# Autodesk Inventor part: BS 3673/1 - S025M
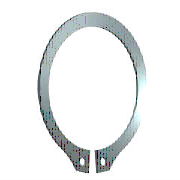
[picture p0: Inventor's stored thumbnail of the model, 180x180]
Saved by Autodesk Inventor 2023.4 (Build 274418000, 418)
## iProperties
Created: 2022-02
Part Number: BS 3673/1 - S025M
Material: Acier, doux
Description: Spécifications des anneaux élastiques - Anneaux élastiques en acier au carbone
Document SubType Name: Modeling
Standard: BS 3673/1
Designer: bruno
Standards Organization: BSI
Language: fr-FR
Size Designation: S025M
Categories: <MemberInstance><Categories><Category DisplayName="Pièces d'arbre" InternalName="7f7aeb1f-a693-4053-b835-cee3144e0d98" Mnemonic="SHFT"><Category DisplayName="An
Density: 7.85 g/cm^3
Appearance: Semi-poli
IsCustomPart: 0
Author: bruno
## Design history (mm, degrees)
sketch "Esquisse1"
  geometry: L1 (-6, 0)-(6, 0) reference; L2 (0, 20.189)-(0, -80.536) reference; L3 (-48.09, 0)-(48.09, 0) reference; L4 (-0.482, -24.403)-(-0.482, -29.508); L5 (-0.483, -6.54)-(-0.482, -13.29); L6 (-2.795, 2.642)-(3.672, 2.642); L7 (0.483, -6.54)-(0.482, -13.29); L8 (0.482, -24.403)-(0.482, -29.508); C1 r 0.965 at (-1.93, -27.461); C2 r 0.965 at (1.93, -27.461); A1 r 11.912 centre (0, -12.5) between (0.482, -24.403) and (-0.482, -24.403); A2 r 14.482 centre (0, -11.84) between (5.101, -25.393) and (-5.101, -25.393); A3 r 17.015 centre (0, -12.5) between (-2.177, -29.375) and (-0.482, -29.508); A4 r 1.93 centre (-1.93, -27.461) between (-3.856, -27.33) and (-2.177, -29.375); A5 r 1.93 centre (-5.781, -27.199) between (-3.856, -27.33) and (-5.101, -25.393); A6 r 1.93 centre (5.781, -27.199) between (5.101, -25.393) and (3.856, -27.33); A7 r 1.93 centre (1.93, -27.461) between (2.177, -29.375) and (3.856, -27.33); A8 r 17.015 centre (0, -12.5) between (0.482, -29.508) and (2.177, -29.375)
  constraints: 16 point on circle, 12 end point, 10 centre point, 9 symmetric about line, 5 point on line, 4 tangent, 3 coincident, 2 horizontal, 1 perpendicular, 1 vertical, 5 other
  dimensions: "d0" = 23.825 diameter of A1 (= ND); "d1" = 5.1054 distance of L4.end L4.start (= SRB2); "d6" = 0.4825 distance between parallel lines of L2 L5 (= 0.25 x SD5); "d7" = 2.642 distance between parallel lines of L6 L3 (= SRB1); "d8" = 0.6605 distance of A1.centre A2.centre (= 0.25 x SRB1); "d9" = 1.93 radius of A4 (= SD5); "d10" = 1.93 radius of A5 (= SD5); "d11" = 1.4475 distance from line of L4 A4.centre (= 0.75 x SD5); "d12" = 1.93 diameter of C1 (= SD5); "d13" = 1.93 diameter of C2 (= SD5); "d14" = 12.5 distance from line of A1.centre L1 (= 0.5 x WD)
extrude "Corps" new body sketch "Esquisse1" distance "d2" = 1.207 (= SD); taper "d3" = 0 deg
workaxis "Work Axis1"
workplane "Work Plane1"
body "Solid1"
other parameters: "WD" = 25 (= WDMIN) [user parameter; used in 1 equation term], "SD" = 1.207 [user parameter; used in 1 equation term], "SRB1" = 2.642 [user parameter; used in 2 equation terms], "ND" = 23.825 [user parameter; used in 2 equation terms], "SRB2" = 5.1054 [user parameter; used in 1 equation term], "SD5" = 1.93 [user parameter; used in 6 equation terms], "d15" = 0, "d16" = 0, "d17" = 0, "d41" = 0, "d42" = 0, "WDMIN" = 25 [user parameter; used in 1 equation term], "SD3" = 23.825 (= ND) [user parameter], "WDMAX" = 25.121 [user parameter]
